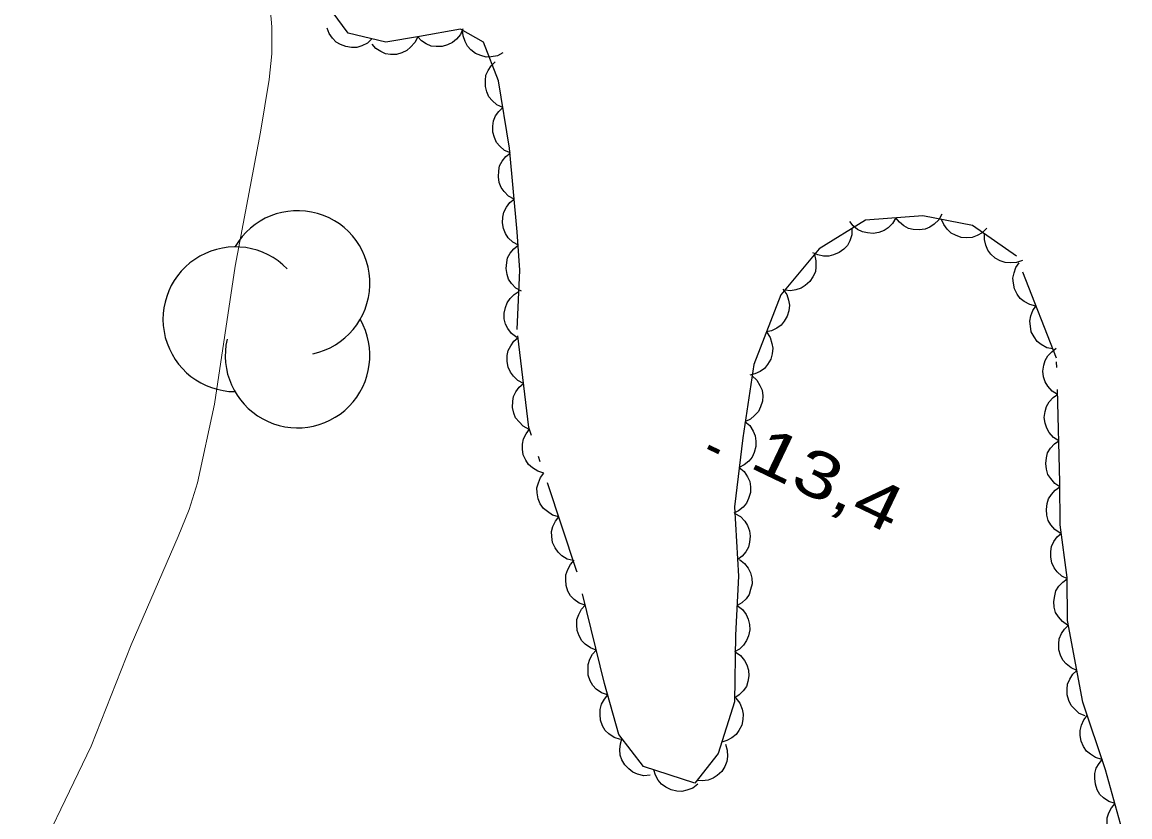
# Model space of a CAD drawing. Extents: x 355726 to 357533, y 5103782 to 5105258.
# Drawn here: x 356188.94 to 356224.9, y 5104866.12 to 5104891.9 of the extents above; entities that cross this region are included whole.
import ezdxf

# ---------------------------------------------------------------- set-up
doc = ezdxf.new("R2010")
doc.units = 0
doc.header["$LTSCALE"] = 0.6
doc.linetypes.add('DOT_DASHED', pattern=[7.7, 5, -1.2, 0.3, -1.2])
doc.linetypes.add('LONG_DASHED', pattern=[7.5, 6, -1.5])
for name, color, linetype, lineweight in [('2', 7, 'LONG_DASHED', 13), ('3', 7, 'Continuous', 140), ('44', 7, 'Continuous', 25)]:
    doc.layers.add(name, color=color, linetype=linetype, lineweight=lineweight)

msp = doc.modelspace()

# ---------------------------------------------------------------- linework, layer by layer
at = {"layer": '2', "linetype": 'Continuous'}
msp.add_lwpolyline([(356188.94, 5104863.76), (356191.18, 5104868.41), (356192.48, 5104871.7), (356194.01, 5104875.21), (356194.36, 5104876.09), (356194.63, 5104876.96), (356195.18, 5104879.51), (356195.85, 5104883.99), (356196.68, 5104888.34), (356196.96, 5104890.04), (356197.05, 5104890.88), (356197.05, 5104891.75), (356196.97, 5104892.63)], dxfattribs=at)
at = {"layer": '3'}
msp.add_line((356211.21, 5104878.12), (356211.57, 5104877.95), dxfattribs=at)
at = {"layer": '44', "linetype": 'DOT_DASHED'}
for points in [[(356219.79, 5104885.31), (356218.18, 5104885.62), (356216.32, 5104885.48), (356214.81, 5104884.55), (356213.57, 5104883.06), (356212.69, 5104880.79), (356212.34, 5104878.41), (356212.07, 5104876.18), (356212.2, 5104873.93), (356212.1, 5104872.01), (356212.07, 5104869.85), (356211.53, 5104868.17), (356210.78, 5104867.21), (356209.11, 5104867.75), (356208.31, 5104868.79), (356207.85, 5104870.44), (356206.94, 5104874.11), (356205.39, 5104878.75), (356205.01, 5104881.93), (356205.1, 5104883.86), (356205.01, 5104885.1), (356204.76, 5104887.82), (356204.4, 5104890), (356203.92, 5104891.26), (356203.17, 5104891.68), (356201.84, 5104891.44), (356200.75, 5104891.26), (356199.52, 5104891.55), (356198.29, 5104893.23)], [(356224.9, 5104864.82), (356224.11, 5104867.64), (356223.37, 5104869.84), (356222.88, 5104872.49), (356222.87, 5104873.88), (356222.64, 5104875.59), (356222.63, 5104876.98), (356222.52, 5104881), (356221.22, 5104884.31), (356219.79, 5104885.31)]]:
    msp.add_lwpolyline(points, dxfattribs=at)
at = {"layer": '44'}
for points in [[(356200.3, 5104891.37), (356200.15, 5104891.22), (356199.97, 5104891.14), (356199.81, 5104891.08), (356199.63, 5104891.08), (356199.45, 5104891.11), (356199.27, 5104891.18), (356199.13, 5104891.26), (356199.01, 5104891.39), (356198.91, 5104891.54), (356198.84, 5104891.71)], [(356203.25, 5104891.69), (356203.17, 5104891.5), (356203.04, 5104891.35), (356202.91, 5104891.24), (356202.75, 5104891.17), (356202.57, 5104891.12), (356202.38, 5104891.12), (356202.22, 5104891.13), (356202.06, 5104891.2), (356201.9, 5104891.3), (356201.78, 5104891.43)], [(356201.78, 5104891.43), (356201.69, 5104891.24), (356201.55, 5104891.09), (356201.43, 5104890.98), (356201.27, 5104890.91), (356201.09, 5104890.86), (356200.9, 5104890.86), (356200.74, 5104890.88), (356200.58, 5104890.95), (356200.42, 5104891.05), (356200.3, 5104891.19)], [(356204.55, 5104890.91), (356204.37, 5104890.81), (356204.17, 5104890.78), (356204, 5104890.77), (356203.83, 5104890.82), (356203.66, 5104890.89), (356203.51, 5104891.01), (356203.4, 5104891.13), (356203.32, 5104891.28), (356203.26, 5104891.46), (356203.24, 5104891.64)], [(356204.54, 5104889.14), (356204.35, 5104889.22), (356204.2, 5104889.36), (356204.09, 5104889.48), (356204.02, 5104889.64), (356203.98, 5104889.82), (356203.98, 5104890.01), (356203.99, 5104890.18), (356204.07, 5104890.34), (356204.17, 5104890.49), (356204.3, 5104890.62)], [(356204.79, 5104887.66), (356204.6, 5104887.74), (356204.45, 5104887.88), (356204.34, 5104888), (356204.27, 5104888.16), (356204.22, 5104888.34), (356204.22, 5104888.53), (356204.24, 5104888.7), (356204.31, 5104888.86), (356204.41, 5104889.01), (356204.54, 5104889.14)], [(356204.91, 5104886.16), (356204.73, 5104886.26), (356204.59, 5104886.41), (356204.49, 5104886.54), (356204.43, 5104886.7), (356204.4, 5104886.89), (356204.41, 5104887.08), (356204.44, 5104887.24), (356204.52, 5104887.39), (356204.64, 5104887.54), (356204.78, 5104887.65)], [(356205.05, 5104884.67), (356204.87, 5104884.77), (356204.72, 5104884.91), (356204.63, 5104885.05), (356204.57, 5104885.21), (356204.53, 5104885.39), (356204.55, 5104885.58), (356204.58, 5104885.74), (356204.66, 5104885.9), (356204.77, 5104886.05), (356204.91, 5104886.16)], [(356218.8, 5104885.67), (356218.7, 5104885.49), (356218.55, 5104885.35), (356218.41, 5104885.25), (356218.25, 5104885.19), (356218.06, 5104885.16), (356217.87, 5104885.18), (356217.71, 5104885.21), (356217.56, 5104885.3), (356217.42, 5104885.41), (356217.3, 5104885.55)], [(356215.88, 5104885.21), (356215.87, 5104885), (356215.81, 5104884.81), (356215.73, 5104884.66), (356215.61, 5104884.54), (356215.46, 5104884.43), (356215.28, 5104884.35), (356215.13, 5104884.31), (356214.95, 5104884.31), (356214.77, 5104884.35), (356214.61, 5104884.42)], [(356217.3, 5104885.55), (356217.2, 5104885.37), (356217.05, 5104885.23), (356216.92, 5104885.14), (356216.75, 5104885.08), (356216.57, 5104885.05), (356216.38, 5104885.07), (356216.22, 5104885.1), (356216.06, 5104885.18), (356215.92, 5104885.3), (356215.81, 5104885.44)], [(356220.26, 5104885.22), (356220.11, 5104885.07), (356219.94, 5104884.98), (356219.78, 5104884.92), (356219.61, 5104884.91), (356219.42, 5104884.92), (356219.24, 5104884.99), (356219.1, 5104885.06), (356218.97, 5104885.19), (356218.86, 5104885.34), (356218.79, 5104885.5)], [(356221.41, 5104884.17), (356221.22, 5104884.1), (356221.02, 5104884.09), (356220.85, 5104884.1), (356220.69, 5104884.16), (356220.53, 5104884.25), (356220.39, 5104884.38), (356220.29, 5104884.51), (356220.22, 5104884.67), (356220.18, 5104884.85), (356220.18, 5104885.03)], [(356205.15, 5104883.17), (356204.97, 5104883.27), (356204.83, 5104883.42), (356204.73, 5104883.56), (356204.68, 5104883.72), (356204.65, 5104883.91), (356204.67, 5104884.1), (356204.7, 5104884.26), (356204.78, 5104884.41), (356204.9, 5104884.55), (356205.04, 5104884.67)], [(356214.66, 5104884.37), (356214.71, 5104884.16), (356214.71, 5104883.96), (356214.69, 5104883.8), (356214.61, 5104883.64), (356214.51, 5104883.49), (356214.36, 5104883.36), (356214.23, 5104883.27), (356214.06, 5104883.22), (356213.88, 5104883.19), (356213.7, 5104883.21)], [(356221.85, 5104882.69), (356221.65, 5104882.74), (356221.47, 5104882.84), (356221.34, 5104882.94), (356221.24, 5104883.08), (356221.16, 5104883.25), (356221.12, 5104883.43), (356221.1, 5104883.6), (356221.14, 5104883.77), (356221.2, 5104883.94), (356221.31, 5104884.09)], [(356205, 5104881.67), (356204.83, 5104881.8), (356204.71, 5104881.96), (356204.63, 5104882.1), (356204.59, 5104882.28), (356204.59, 5104882.46), (356204.63, 5104882.65), (356204.68, 5104882.8), (356204.78, 5104882.94), (356204.91, 5104883.07), (356205.07, 5104883.17)], [(356213.64, 5104883.24), (356213.76, 5104883.07), (356213.82, 5104882.88), (356213.85, 5104882.72), (356213.83, 5104882.54), (356213.78, 5104882.36), (356213.68, 5104882.2), (356213.58, 5104882.07), (356213.44, 5104881.97), (356213.27, 5104881.89), (356213.1, 5104881.85)], [(356222.4, 5104881.3), (356222.2, 5104881.34), (356222.02, 5104881.44), (356221.89, 5104881.54), (356221.79, 5104881.69), (356221.7, 5104881.85), (356221.67, 5104882.04), (356221.65, 5104882.2), (356221.69, 5104882.37), (356221.75, 5104882.55), (356221.85, 5104882.69)], [(356205.22, 5104880.18), (356205.03, 5104880.28), (356204.89, 5104880.42), (356204.79, 5104880.55), (356204.72, 5104880.71), (356204.68, 5104880.89), (356204.69, 5104881.09), (356204.72, 5104881.25), (356204.8, 5104881.4), (356204.9, 5104881.55), (356205.04, 5104881.67)], [(356213.1, 5104881.85), (356213.22, 5104881.67), (356213.28, 5104881.48), (356213.31, 5104881.32), (356213.29, 5104881.14), (356213.24, 5104880.97), (356213.14, 5104880.8), (356213.04, 5104880.67), (356212.9, 5104880.57), (356212.73, 5104880.49), (356212.56, 5104880.45)], [(356222.55, 5104879.82), (356222.38, 5104879.93), (356222.24, 5104880.09), (356222.15, 5104880.23), (356222.1, 5104880.39), (356222.08, 5104880.58), (356222.11, 5104880.77), (356222.15, 5104880.93), (356222.24, 5104881.08), (356222.37, 5104881.21), (356222.51, 5104881.32)], [(356205.4, 5104878.69), (356205.21, 5104878.79), (356205.07, 5104878.93), (356204.96, 5104879.06), (356204.9, 5104879.22), (356204.86, 5104879.4), (356204.87, 5104879.6), (356204.89, 5104879.76), (356204.97, 5104879.91), (356205.08, 5104880.06), (356205.22, 5104880.18)], [(356212.64, 5104880.43), (356212.79, 5104880.29), (356212.89, 5104880.11), (356212.96, 5104879.96), (356212.98, 5104879.78), (356212.97, 5104879.6), (356212.91, 5104879.42), (356212.84, 5104879.27), (356212.72, 5104879.14), (356212.58, 5104879.02), (356212.42, 5104878.94)], [(356222.59, 5104878.32), (356222.42, 5104878.43), (356222.28, 5104878.59), (356222.2, 5104878.73), (356222.15, 5104878.89), (356222.12, 5104879.08), (356222.15, 5104879.27), (356222.19, 5104879.43), (356222.28, 5104879.58), (356222.41, 5104879.72), (356222.55, 5104879.82)], [(356212.4, 5104878.94), (356212.56, 5104878.81), (356212.67, 5104878.63), (356212.74, 5104878.48), (356212.76, 5104878.31), (356212.76, 5104878.13), (356212.7, 5104877.94), (356212.64, 5104877.79), (356212.53, 5104877.66), (356212.38, 5104877.54), (356212.22, 5104877.45)], [(356205.88, 5104877.27), (356205.68, 5104877.33), (356205.51, 5104877.44), (356205.38, 5104877.55), (356205.29, 5104877.69), (356205.21, 5104877.86), (356205.18, 5104878.05), (356205.18, 5104878.21), (356205.22, 5104878.38), (356205.3, 5104878.55), (356205.41, 5104878.7)], [(356222.63, 5104876.82), (356222.46, 5104876.93), (356222.33, 5104877.09), (356222.24, 5104877.23), (356222.19, 5104877.4), (356222.17, 5104877.58), (356222.19, 5104877.77), (356222.23, 5104877.93), (356222.32, 5104878.08), (356222.45, 5104878.22), (356222.59, 5104878.32)], [(356212.22, 5104877.45), (356212.38, 5104877.32), (356212.49, 5104877.15), (356212.56, 5104877), (356212.58, 5104876.82), (356212.58, 5104876.64), (356212.52, 5104876.45), (356212.46, 5104876.3), (356212.35, 5104876.17), (356212.2, 5104876.05), (356212.04, 5104875.97)], [(356206.36, 5104875.85), (356206.16, 5104875.91), (356205.99, 5104876.02), (356205.86, 5104876.12), (356205.76, 5104876.27), (356205.69, 5104876.44), (356205.66, 5104876.63), (356205.65, 5104876.79), (356205.7, 5104876.96), (356205.77, 5104877.13), (356205.88, 5104877.27)], [(356222.64, 5104875.32), (356222.47, 5104875.44), (356222.34, 5104875.59), (356222.25, 5104875.73), (356222.21, 5104875.9), (356222.19, 5104876.09), (356222.22, 5104876.28), (356222.26, 5104876.43), (356222.36, 5104876.58), (356222.48, 5104876.72), (356222.63, 5104876.82)], [(356206.83, 5104874.43), (356206.63, 5104874.48), (356206.46, 5104874.59), (356206.34, 5104874.7), (356206.24, 5104874.85), (356206.16, 5104875.02), (356206.14, 5104875.21), (356206.13, 5104875.37), (356206.17, 5104875.54), (356206.25, 5104875.71), (356206.36, 5104875.85)], [(356212.08, 5104875.96), (356212.26, 5104875.86), (356212.4, 5104875.71), (356212.49, 5104875.57), (356212.55, 5104875.4), (356212.57, 5104875.22), (356212.55, 5104875.03), (356212.52, 5104874.87), (356212.43, 5104874.72), (356212.31, 5104874.58), (356212.17, 5104874.47)], [(356222.88, 5104873.84), (356222.69, 5104873.93), (356222.54, 5104874.07), (356222.44, 5104874.2), (356222.37, 5104874.36), (356222.33, 5104874.54), (356222.34, 5104874.73), (356222.36, 5104874.89), (356222.43, 5104875.05), (356222.54, 5104875.2), (356222.68, 5104875.32)], [(356207.22, 5104872.98), (356207.02, 5104873.05), (356206.86, 5104873.17), (356206.74, 5104873.29), (356206.66, 5104873.44), (356206.6, 5104873.62), (356206.59, 5104873.81), (356206.59, 5104873.97), (356206.65, 5104874.14), (356206.74, 5104874.3), (356206.86, 5104874.44)], [(356212.23, 5104874.47), (356212.39, 5104874.34), (356212.51, 5104874.18), (356212.59, 5104874.03), (356212.63, 5104873.86), (356212.64, 5104873.68), (356212.59, 5104873.49), (356212.54, 5104873.33), (356212.44, 5104873.19), (356212.3, 5104873.06), (356212.15, 5104872.97)], [(356222.88, 5104872.34), (356222.71, 5104872.45), (356222.58, 5104872.61), (356222.49, 5104872.75), (356222.44, 5104872.92), (356222.43, 5104873.1), (356222.46, 5104873.29), (356222.5, 5104873.45), (356222.6, 5104873.6), (356222.72, 5104873.73), (356222.87, 5104873.84)], [(356207.58, 5104871.52), (356207.39, 5104871.6), (356207.22, 5104871.72), (356207.11, 5104871.83), (356207.02, 5104871.99), (356206.96, 5104872.16), (356206.95, 5104872.35), (356206.95, 5104872.52), (356207.01, 5104872.68), (356207.1, 5104872.85), (356207.22, 5104872.98)], [(356212.15, 5104872.97), (356212.32, 5104872.84), (356212.44, 5104872.68), (356212.51, 5104872.53), (356212.55, 5104872.36), (356212.56, 5104872.18), (356212.52, 5104871.99), (356212.46, 5104871.84), (356212.36, 5104871.69), (356212.23, 5104871.56), (356212.07, 5104871.47)], [(356223.18, 5104870.86), (356222.99, 5104870.95), (356222.83, 5104871.08), (356222.72, 5104871.2), (356222.65, 5104871.36), (356222.6, 5104871.54), (356222.6, 5104871.73), (356222.61, 5104871.89), (356222.68, 5104872.06), (356222.78, 5104872.21), (356222.91, 5104872.34)], [(356207.94, 5104870.07), (356207.75, 5104870.14), (356207.58, 5104870.26), (356207.47, 5104870.38), (356207.38, 5104870.53), (356207.32, 5104870.71), (356207.31, 5104870.9), (356207.31, 5104871.06), (356207.37, 5104871.23), (356207.46, 5104871.39), (356207.58, 5104871.52)], [(356212.09, 5104871.47), (356212.26, 5104871.35), (356212.39, 5104871.19), (356212.47, 5104871.05), (356212.52, 5104870.88), (356212.53, 5104870.69), (356212.5, 5104870.51), (356212.45, 5104870.35), (356212.35, 5104870.2), (356212.22, 5104870.07), (356212.07, 5104869.97)], [(356223.45, 5104869.39), (356223.26, 5104869.47), (356223.11, 5104869.61), (356223, 5104869.73), (356222.92, 5104869.89), (356222.87, 5104870.07), (356222.87, 5104870.26), (356222.88, 5104870.42), (356222.95, 5104870.58), (356223.05, 5104870.74), (356223.18, 5104870.86)], [(356208.36, 5104868.63), (356208.16, 5104868.69), (356207.99, 5104868.81), (356207.87, 5104868.92), (356207.78, 5104869.07), (356207.72, 5104869.25), (356207.7, 5104869.44), (356207.7, 5104869.6), (356207.75, 5104869.77), (356207.84, 5104869.93), (356207.95, 5104870.07)], [(356212.11, 5104869.97), (356212.24, 5104869.8), (356212.31, 5104869.61), (356212.35, 5104869.45), (356212.34, 5104869.27), (356212.3, 5104869.09), (356212.21, 5104868.92), (356212.12, 5104868.79), (356211.98, 5104868.68), (356211.82, 5104868.59), (356211.65, 5104868.54)], [(356223.99, 5104867.98), (356223.79, 5104868.04), (356223.62, 5104868.15), (356223.49, 5104868.25), (356223.4, 5104868.4), (356223.32, 5104868.57), (356223.29, 5104868.76), (356223.29, 5104868.92), (356223.33, 5104869.09), (356223.41, 5104869.26), (356223.52, 5104869.41)], [(356209.33, 5104867.47), (356209.12, 5104867.45), (356208.92, 5104867.5), (356208.77, 5104867.56), (356208.63, 5104867.67), (356208.5, 5104867.8), (356208.41, 5104867.97), (356208.35, 5104868.12), (356208.34, 5104868.3), (356208.36, 5104868.48), (356208.41, 5104868.65)], [(356211.77, 5104868.47), (356211.83, 5104868.28), (356211.84, 5104868.07), (356211.82, 5104867.91), (356211.75, 5104867.75), (356211.65, 5104867.59), (356211.5, 5104867.46), (356211.37, 5104867.37), (356211.21, 5104867.31), (356211.02, 5104867.28), (356210.84, 5104867.29)], [(356224.42, 5104866.55), (356224.22, 5104866.61), (356224.05, 5104866.73), (356223.93, 5104866.84), (356223.84, 5104866.99), (356223.78, 5104867.17), (356223.76, 5104867.36), (356223.76, 5104867.52), (356223.81, 5104867.69), (356223.9, 5104867.85), (356224.01, 5104867.99)], [(356210.88, 5104867.18), (356210.71, 5104867.05), (356210.52, 5104866.98), (356210.36, 5104866.94), (356210.19, 5104866.95), (356210.01, 5104866.99), (356209.84, 5104867.08), (356209.7, 5104867.17), (356209.59, 5104867.31), (356209.5, 5104867.47), (356209.45, 5104867.64)], [(356224.82, 5104865.1), (356224.62, 5104865.17), (356224.46, 5104865.28), (356224.34, 5104865.4), (356224.25, 5104865.55), (356224.18, 5104865.72), (356224.16, 5104865.91), (356224.16, 5104866.08), (356224.22, 5104866.24), (356224.3, 5104866.41), (356224.42, 5104866.55)]]:
    msp.add_lwpolyline(points, dxfattribs=at)
for centre, start, end in [((356197.881, 5104883.438), 282.2692, 149.7263), ((356195.861, 5104882.263), 44.1154, 269.804), ((356197.881, 5104881.089), 166.9369, 29.6212)]:
    msp.add_arc(centre, 2.349, start, end, dxfattribs=at)

# ---------------------------------------------------------------- texts
at = {"layer": '3', "width": 1.3}
msp.add_text('13,4   ', height=1.5, rotation=334.423, dxfattribs=at).set_placement((356212.5, 5104877.48))

doc.saveas('drawing.dxf')
